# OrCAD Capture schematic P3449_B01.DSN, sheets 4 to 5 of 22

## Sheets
4 0018_CAM Connector: size Custom
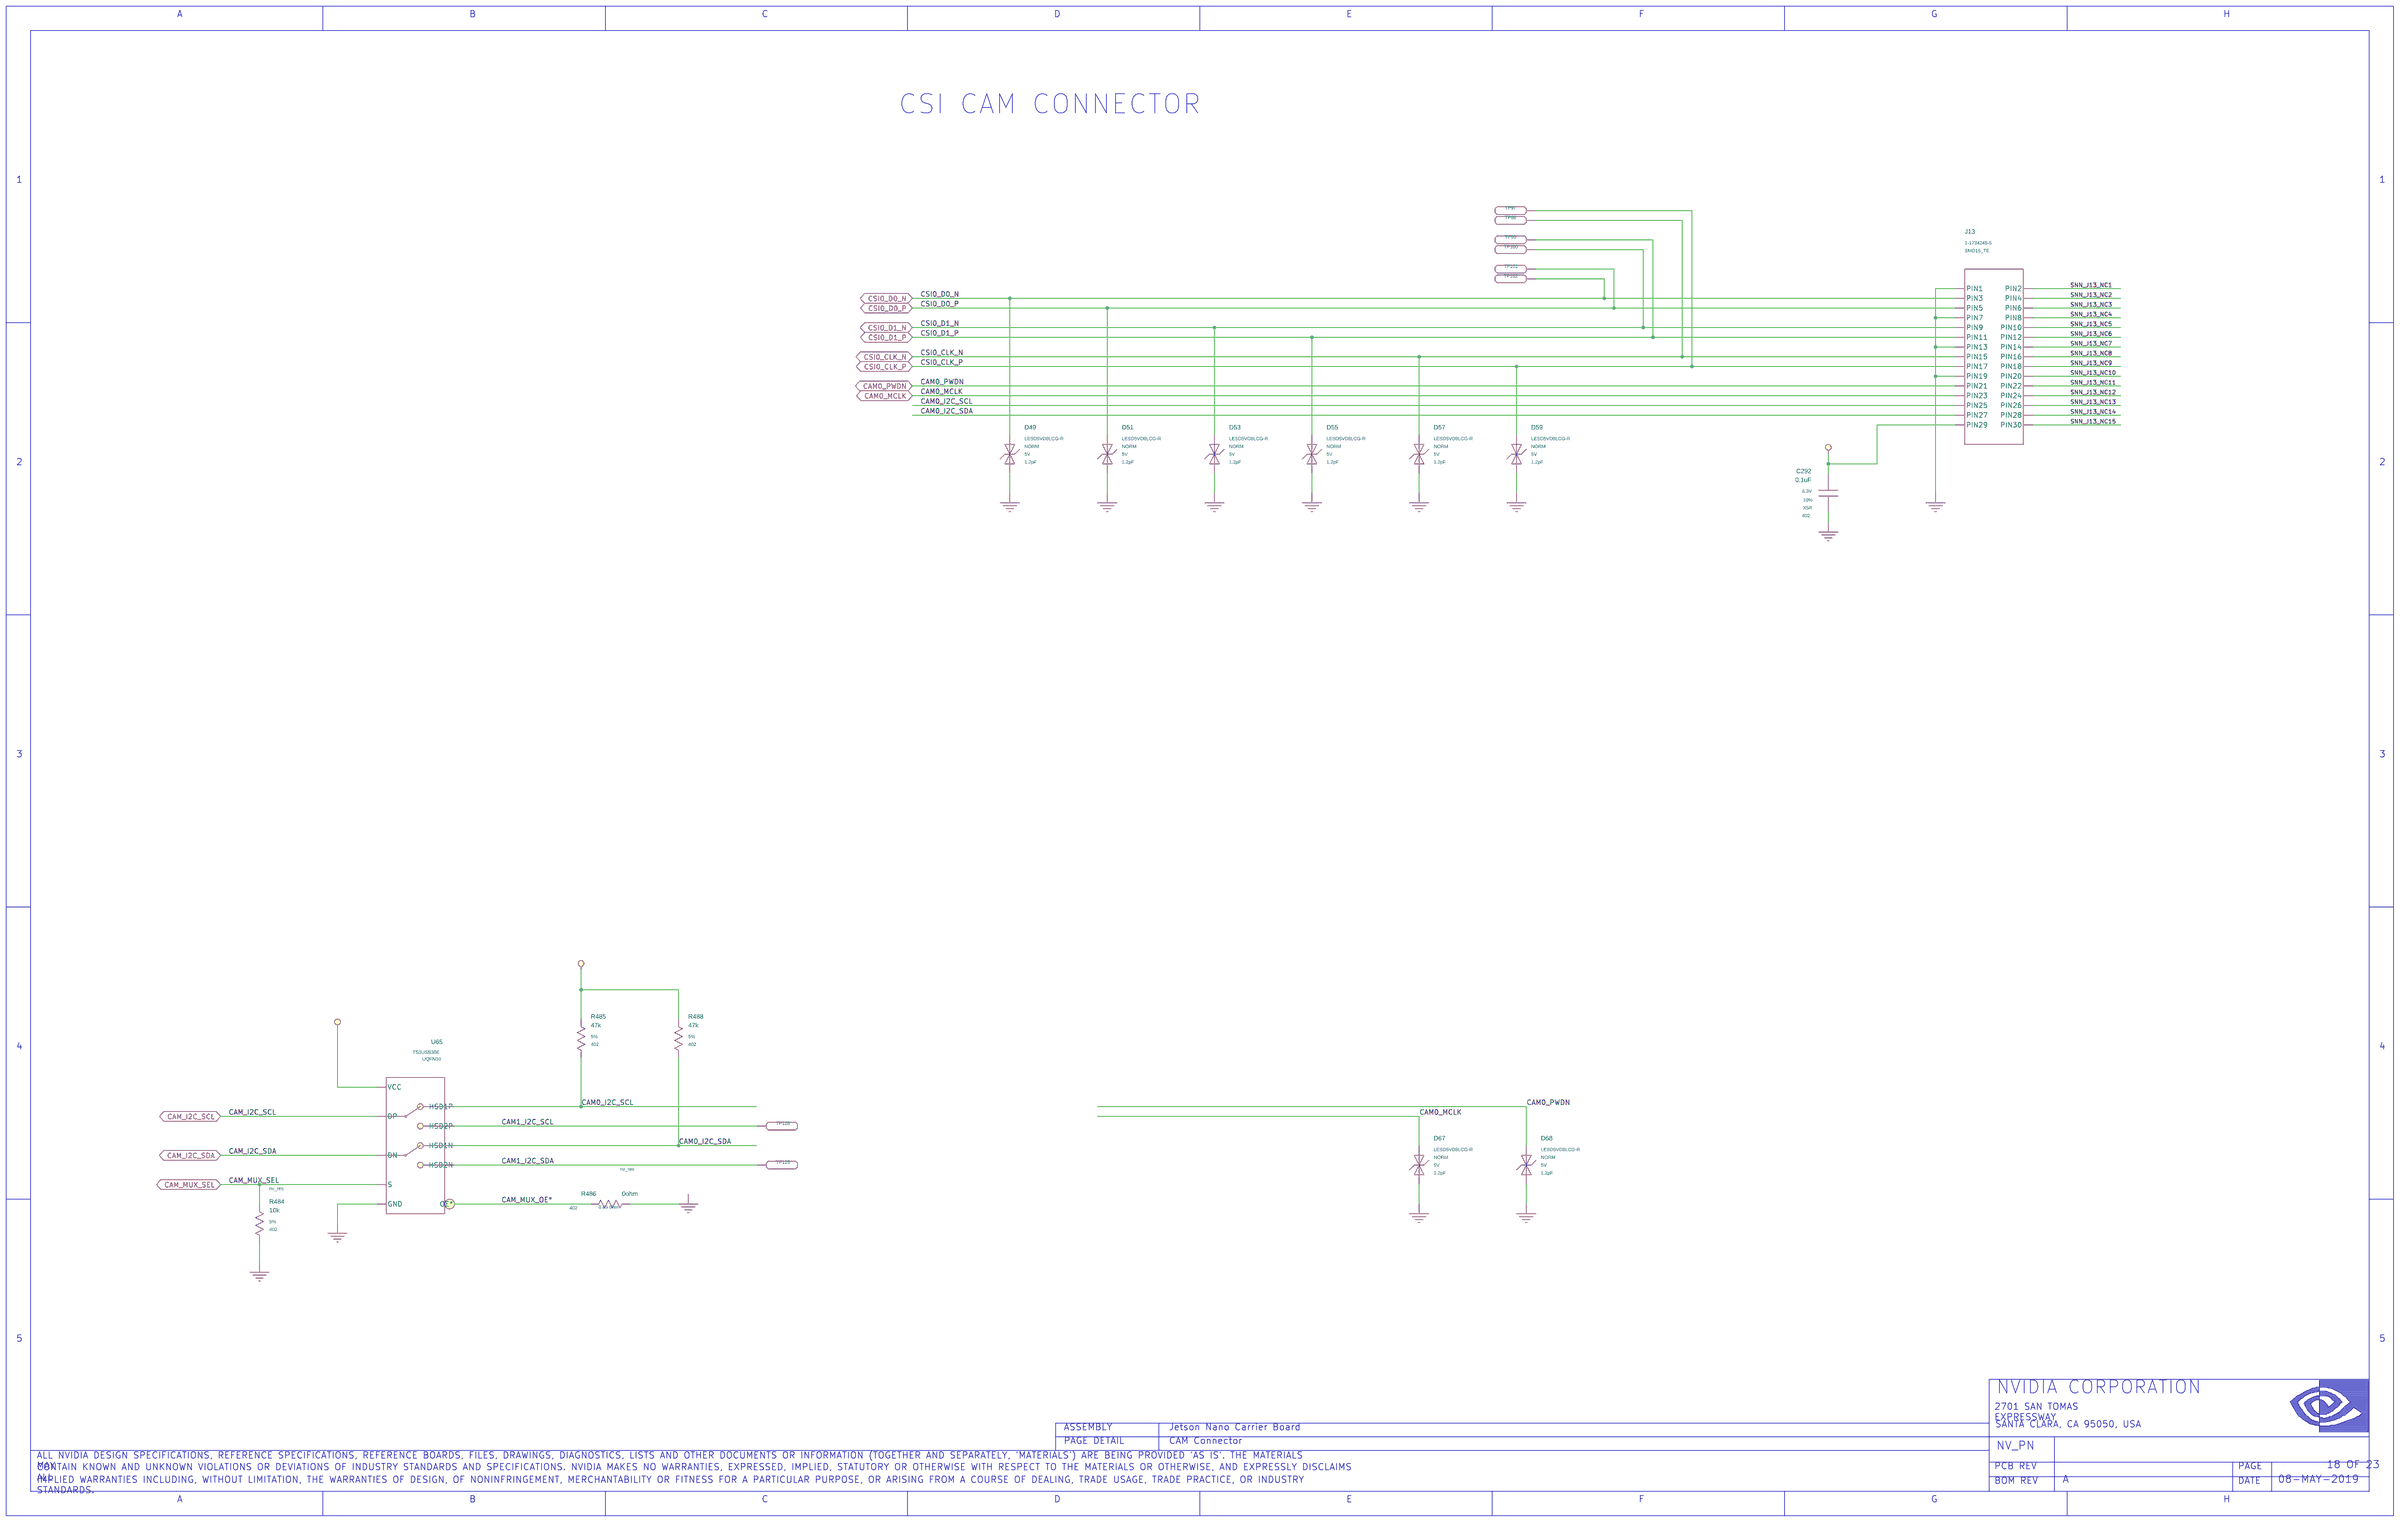
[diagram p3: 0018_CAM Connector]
5 0017_DisplayPort: size Custom
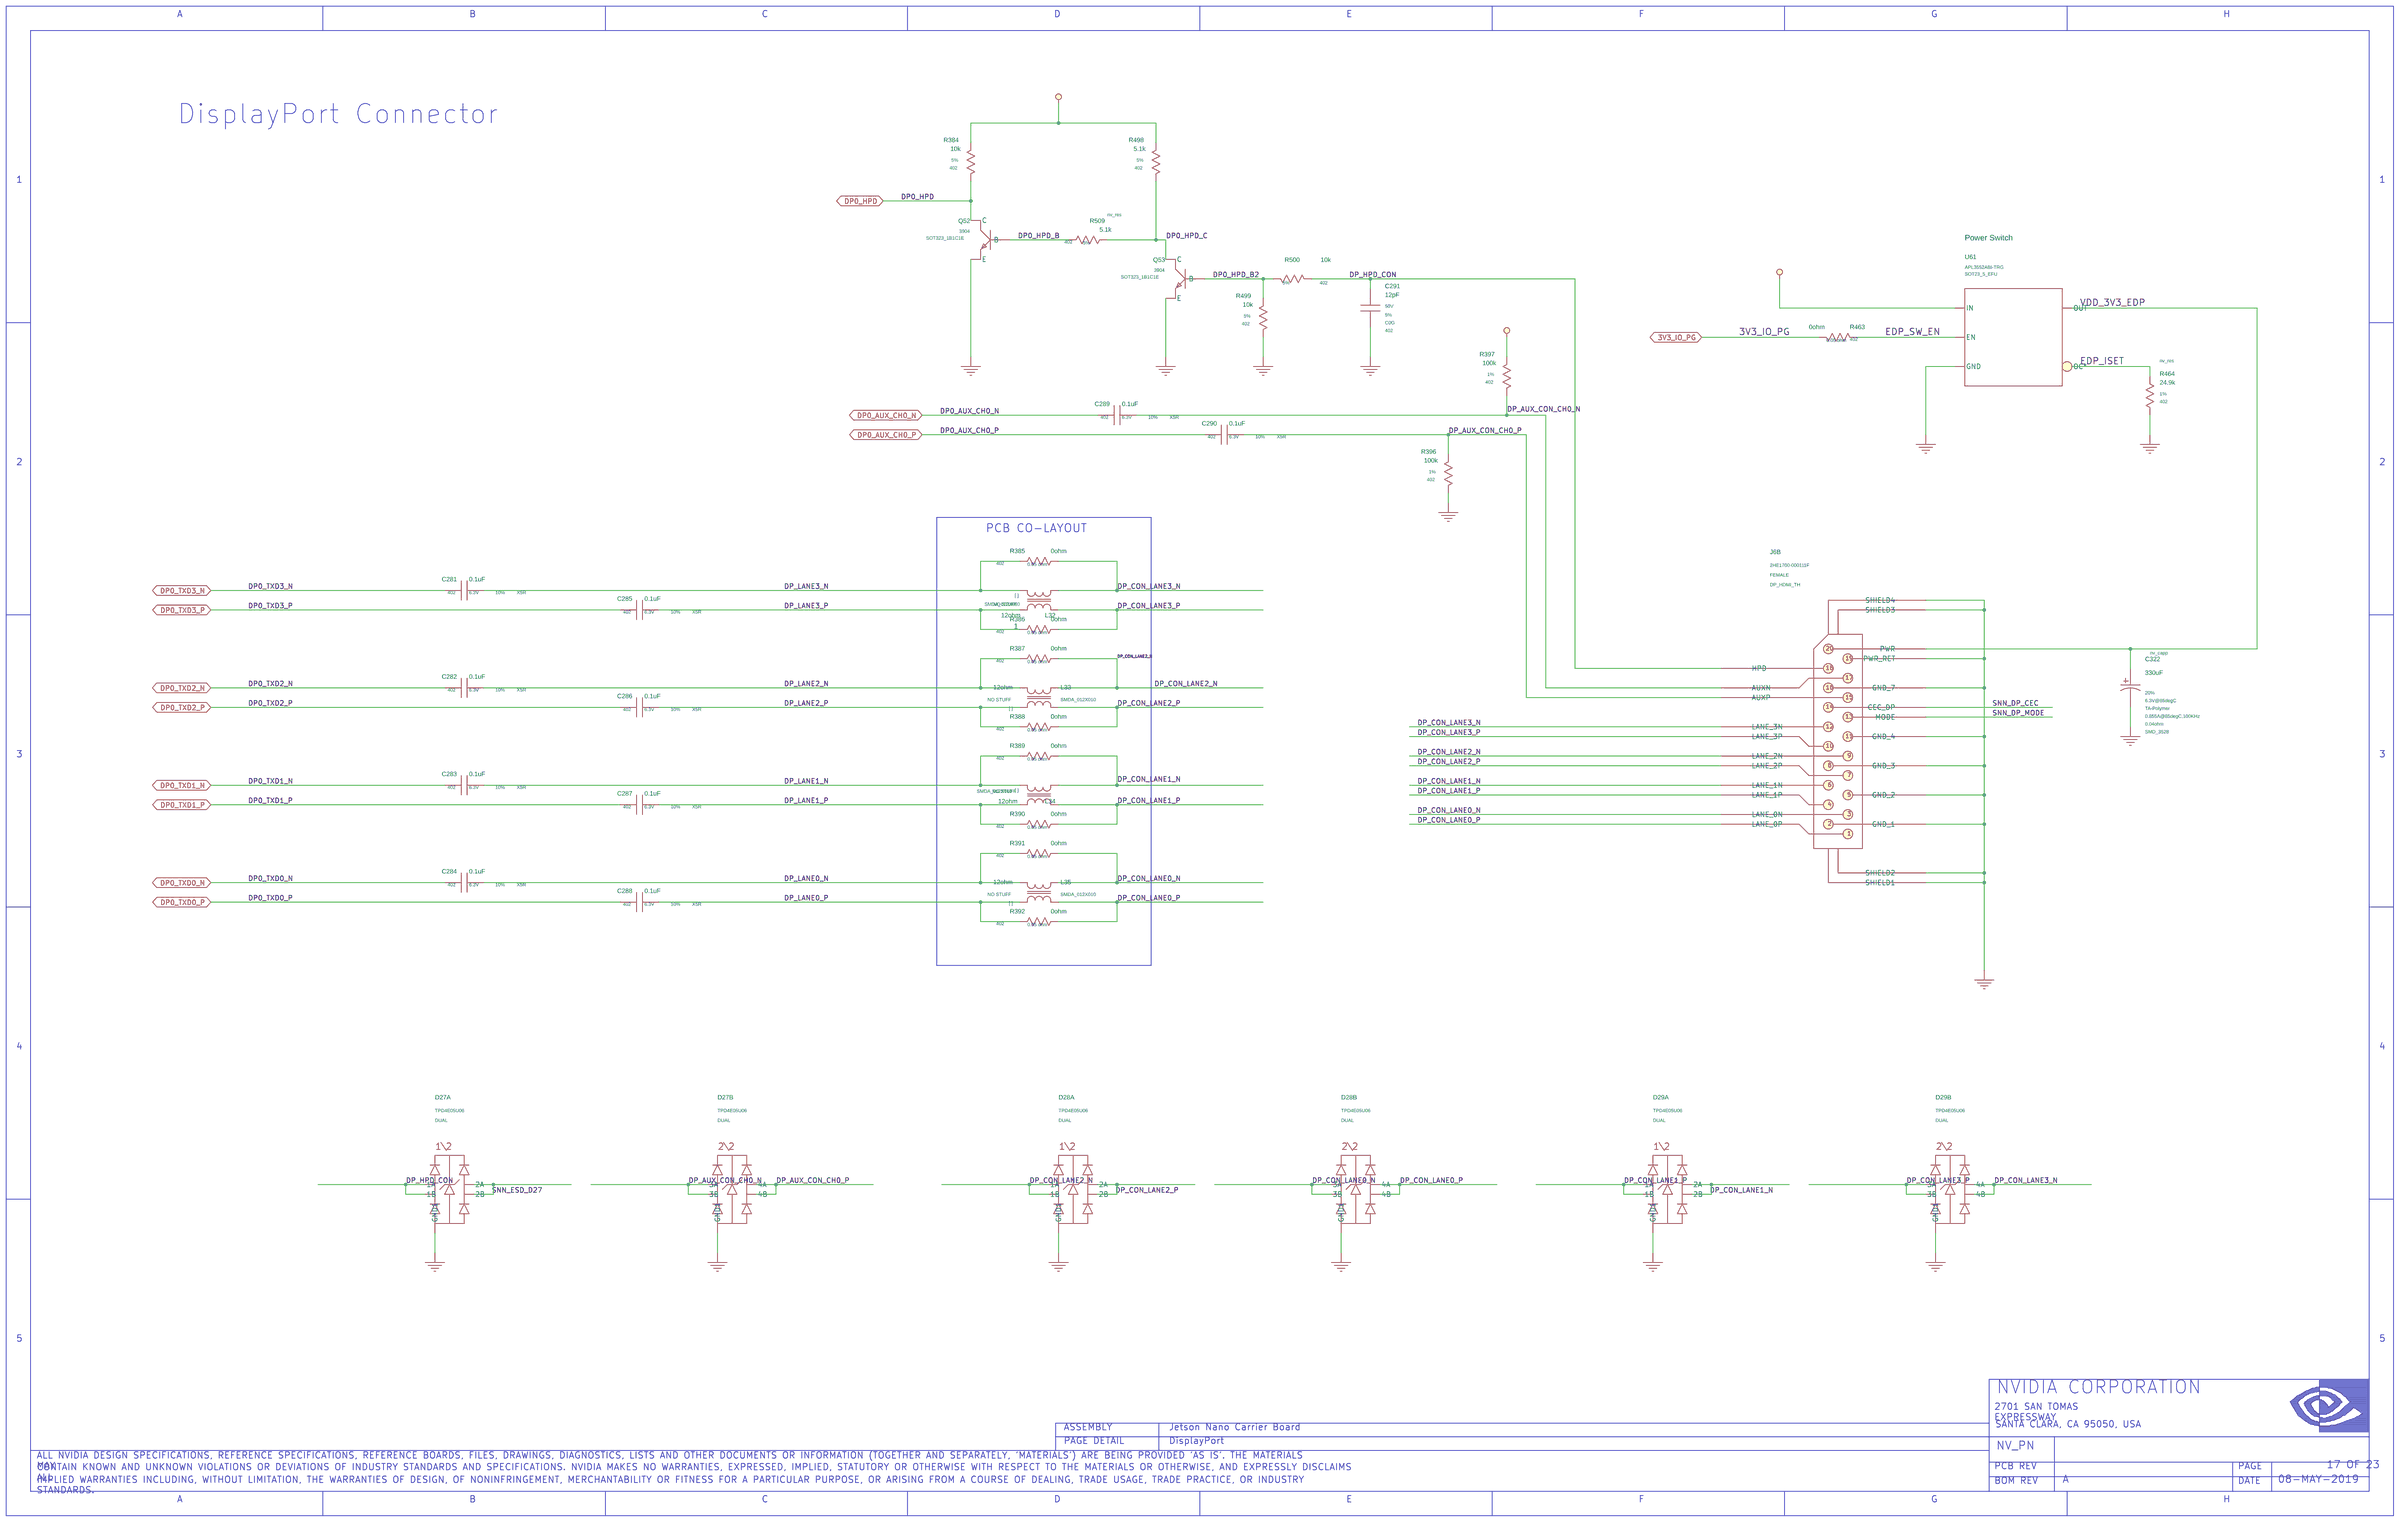
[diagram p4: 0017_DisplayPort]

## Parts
sheet 0017_DisplayPort
C281  0.1uF  [402]
C282  0.1uF  [402]
C283  0.1uF  [402]
C284  0.1uF  [402]
C285  0.1uF  [402]
C286  0.1uF  [402]
C287  0.1uF  [402]
C288  0.1uF  [402]
C289  0.1uF  [402]
C290  0.1uF  [402]
C291  12pF  [402]
C322  330uF  [CAP_SMD_3528]
D27  D_ESD_DIFFPAIR  [TSLP10_P050_025X010]  (sections A,B)
D28  D_ESD_DIFFPAIR  [TSLP10_P050_025X010]  (sections A,B)
D29  D_ESD_DIFFPAIR  [TSLP10_P050_025X010]  (sections A,B)
J6  CON_HDMI_DISPLAYPORT  [CON_HDMI_019_DP_020_TH_RA_F_181X180_B]  (sections A,B)
L32  12ohm  [IND_NONRKO_SMD_012X010]
L33  12ohm  [IND_NONRKO_SMD_012X010]
L34  12ohm  [IND_NONRKO_SMD_012X010]
L35  12ohm  [IND_NONRKO_SMD_012X010]
Q52  Q_NPN  [SOT323_D]
Q53  Q_NPN  [SOT323_D]
R384  10k  [402]
R385  0ohm  [402]
R386  0ohm  [402]
R387  0ohm  [402]
R388  0ohm  [402]
R389  0ohm  [402]
R390  0ohm  [402]
R391  0ohm  [402]
R392  0ohm  [402]
R396  100k  [402]
R397  100k  [402]
R463  0ohm  [402]
R464  24.9k  [402]
R498  5.1k  [402]
R499  10k  [402]
R500  10k  [402]
R509  5.1k  [402]
U61  U_PWR_SW_UL  [SOT23_5]
sheet 0018_CAM Connector
C292  0.1uF  [402]
D49  D_ESD  [DIODE_SMD_010X060]
D51  D_ESD  [DIODE_SMD_010X060]
D53  D_ESD  [DIODE_SMD_010X060]
D55  D_ESD  [DIODE_SMD_010X060]
D57  D_ESD  [DIODE_SMD_010X060]
D59  D_ESD  [DIODE_SMD_010X060]
D67  D_ESD  [DIODE_SMD_010X060]
D68  D_ESD  [DIODE_SMD_010X060]
J13  CON_FPC_15  [CON_FFC_030_SMD_ST_F_P010_ZIF]
R484  10k  [402]
R485  47k  [402]
R486  0ohm  [402]
R488  47k  [402]
TP97  LABTESTPOINT  [LTPB071C125D045C025P]
TP98  LABTESTPOINT  [LTPB071C125D045C025P]
TP99  LABTESTPOINT  [LTPB071C125D045C025P]
TP100  LABTESTPOINT  [LTPB071C125D045C025P]
TP101  LABTESTPOINT  [LTPB071C125D045C025P]
TP102  LABTESTPOINT  [LTPB071C125D045C025P]
TP128  LABTESTPOINT  [LTPB071C125D045C025P]
TP129  LABTESTPOINT  [LTPB071C125D045C025P]
U65  U_SW_ANA_USB  [QFN010R_P040_0018X0014]

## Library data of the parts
C281 = C: ASSEMBLY: EDP; CDS_LIB: discrete; CDS_PART_NAME: C_0402-0.1UF,X5R,10%,6.3V,039-0007-000; CDS_PHYS_PART_NAME: C_0402-0.1UF,X5R,10%,6.3V,039-0007-000-0.1UF,039-0007-000; CDS_SEC: 1; DEVICE_TYPENAME: C_0402-01UFX5R1063V039-0007-000-01UF039-0007-000; DRAWING: @P3449_B01_LIB.P3449_B01(SCH_1):PAGE17; MAT: X5R; MAX_VOLTAGE: 6.3V; NO_XNET: 1; NV_PN: 039-0007-000; PATH: I22; PHYS_PAGE: 17; ROT: 0; SEC: 1; SIGNAL_MODEL: nv_cap; TOL: 10%; VER: 2; XY: (-9800,4600)
C282 = C: ASSEMBLY: EDP; CDS_LIB: discrete; CDS_PART_NAME: C_0402-0.1UF,X5R,10%,6.3V,039-0007-000; CDS_PHYS_PART_NAME: C_0402-0.1UF,X5R,10%,6.3V,039-0007-000-0.1UF,039-0007-000; CDS_SEC: 1; DEVICE_TYPENAME: C_0402-01UFX5R1063V039-0007-000-01UF039-0007-000; DRAWING: @P3449_B01_LIB.P3449_B01(SCH_1):PAGE17; MAT: X5R; MAX_VOLTAGE: 6.3V; NO_XNET: 1; NV_PN: 039-0007-000; PATH: I28; PHYS_PAGE: 17; ROT: 0; SEC: 1; SIGNAL_MODEL: nv_cap; TOL: 10%; VER: 2; XY: (-9800,4100)
C283 = C: ASSEMBLY: EDP; CDS_LIB: discrete; CDS_PART_NAME: C_0402-0.1UF,X5R,10%,6.3V,039-0007-000; CDS_PHYS_PART_NAME: C_0402-0.1UF,X5R,10%,6.3V,039-0007-000-0.1UF,039-0007-000; CDS_SEC: 1; DEVICE_TYPENAME: C_0402-01UFX5R1063V039-0007-000-01UF039-0007-000; DRAWING: @P3449_B01_LIB.P3449_B01(SCH_1):PAGE17; MAT: X5R; MAX_VOLTAGE: 6.3V; NO_XNET: 1; NV_PN: 039-0007-000; PATH: I29; PHYS_PAGE: 17; ROT: 0; SEC: 1; SIGNAL_MODEL: nv_cap; TOL: 10%; VER: 2; XY: (-9800,3600)
C284 = C: ASSEMBLY: EDP; CDS_LIB: discrete; CDS_PART_NAME: C_0402-0.1UF,X5R,10%,6.3V,039-0007-000; CDS_PHYS_PART_NAME: C_0402-0.1UF,X5R,10%,6.3V,039-0007-000-0.1UF,039-0007-000; CDS_SEC: 1; DEVICE_TYPENAME: C_0402-01UFX5R1063V039-0007-000-01UF039-0007-000; DRAWING: @P3449_B01_LIB.P3449_B01(SCH_1):PAGE17; MAT: X5R; MAX_VOLTAGE: 6.3V; NO_XNET: 1; NV_PN: 039-0007-000; PATH: I27; PHYS_PAGE: 17; ROT: 0; SEC: 1; SIGNAL_MODEL: nv_cap; TOL: 10%; VER: 2; XY: (-9800,3100)
C285 = C: ASSEMBLY: EDP; CDS_LIB: discrete; CDS_PART_NAME: C_0402-0.1UF,X5R,10%,6.3V,039-0007-000; CDS_PHYS_PART_NAME: C_0402-0.1UF,X5R,10%,6.3V,039-0007-000-0.1UF,039-0007-000; CDS_SEC: 1; DEVICE_TYPENAME: C_0402-01UFX5R1063V039-0007-000-01UF039-0007-000; DRAWING: @P3449_B01_LIB.P3449_B01(SCH_1):PAGE17; MAT: X5R; MAX_VOLTAGE: 6.3V; NO_XNET: 1; NV_PN: 039-0007-000; PATH: I23; PHYS_PAGE: 17; ROT: 0; SEC: 1; SIGNAL_MODEL: nv_cap; TOL: 10%; VER: 2; XY: (-8900,4500)
C286 = C: ASSEMBLY: EDP; CDS_LIB: discrete; CDS_PART_NAME: C_0402-0.1UF,X5R,10%,6.3V,039-0007-000; CDS_PHYS_PART_NAME: C_0402-0.1UF,X5R,10%,6.3V,039-0007-000-0.1UF,039-0007-000; CDS_SEC: 1; DEVICE_TYPENAME: C_0402-01UFX5R1063V039-0007-000-01UF039-0007-000; DRAWING: @P3449_B01_LIB.P3449_B01(SCH_1):PAGE17; MAT: X5R; MAX_VOLTAGE: 6.3V; NO_XNET: 1; NV_PN: 039-0007-000; PATH: I24; PHYS_PAGE: 17; ROT: 0; SEC: 1; SIGNAL_MODEL: nv_cap; TOL: 10%; VER: 2; XY: (-8900,4000)
C287 = C: ASSEMBLY: EDP; CDS_LIB: discrete; CDS_PART_NAME: C_0402-0.1UF,X5R,10%,6.3V,039-0007-000; CDS_PHYS_PART_NAME: C_0402-0.1UF,X5R,10%,6.3V,039-0007-000-0.1UF,039-0007-000; CDS_SEC: 1; DEVICE_TYPENAME: C_0402-01UFX5R1063V039-0007-000-01UF039-0007-000; DRAWING: @P3449_B01_LIB.P3449_B01(SCH_1):PAGE17; MAT: X5R; MAX_VOLTAGE: 6.3V; NO_XNET: 1; NV_PN: 039-0007-000; PATH: I25; PHYS_PAGE: 17; ROT: 0; SEC: 1; SIGNAL_MODEL: nv_cap; TOL: 10%; VER: 2; XY: (-8900,3500)
C288 = C: ASSEMBLY: EDP; CDS_LIB: discrete; CDS_PART_NAME: C_0402-0.1UF,X5R,10%,6.3V,039-0007-000; CDS_PHYS_PART_NAME: C_0402-0.1UF,X5R,10%,6.3V,039-0007-000-0.1UF,039-0007-000; CDS_SEC: 1; DEVICE_TYPENAME: C_0402-01UFX5R1063V039-0007-000-01UF039-0007-000; DRAWING: @P3449_B01_LIB.P3449_B01(SCH_1):PAGE17; MAT: X5R; MAX_VOLTAGE: 6.3V; NO_XNET: 1; NV_PN: 039-0007-000; PATH: I26; PHYS_PAGE: 17; ROT: 0; SEC: 1; SIGNAL_MODEL: nv_cap; TOL: 10%; VER: 2; XY: (-8900,3000)
C289 = C: ASSEMBLY: EDP; CDS_LIB: discrete; CDS_PART_NAME: C_0402-0.1UF,X5R,10%,6.3V,039-0007-000; CDS_PHYS_PART_NAME: C_0402-0.1UF,X5R,10%,6.3V,039-0007-000-0.1UF,039-0007-000; CDS_SEC: 1; DEVICE_TYPENAME: C_0402-01UFX5R1063V039-0007-000-01UF039-0007-000; DRAWING: @P3449_B01_LIB.P3449_B01(SCH_1):PAGE17; MAT: X5R; MAX_VOLTAGE: 6.3V; NV_PN: 039-0007-000; PATH: I38; PHYS_PAGE: 17; ROT: 0; SEC: 1; SIGNAL_MODEL: nv_cap; TOL: 10%; VER: 2; XY: (-6450,5500)
C290 = C: ASSEMBLY: EDP; CDS_LIB: discrete; CDS_PART_NAME: C_0402-0.1UF,X5R,10%,6.3V,039-0007-000; CDS_PHYS_PART_NAME: C_0402-0.1UF,X5R,10%,6.3V,039-0007-000-0.1UF,039-0007-000; CDS_SEC: 1; DEVICE_TYPENAME: C_0402-01UFX5R1063V039-0007-000-01UF039-0007-000; DRAWING: @P3449_B01_LIB.P3449_B01(SCH_1):PAGE17; MAT: X5R; MAX_VOLTAGE: 6.3V; NV_PN: 039-0007-000; PATH: I39; PHYS_PAGE: 17; ROT: 0; SEC: 1; SIGNAL_MODEL: nv_cap; TOL: 10%; VER: 2; XY: (-5900,5400)
C291 = C#1: ASSEMBLY: EDP; CDS_LIB: discrete; CDS_PART_NAME: C_0402-12PF,C0G,5%,50V,035-0014-000; CDS_PHYS_PART_NAME: C_0402-12PF,C0G,5%,50V,035-0014-000-035-0014-000,12PF; CDS_SEC: 1; CHIPS_PART_NAME: C; DEVICE_TYPENAME: C_0402-12PFC0G550V035-0014-000-035-0014-00012PF; DRAWING: @P3449_B01_LIB.P3449_B01(SCH_1):PAGE17; ESL: N/A; ESR: N/A; MAT: C0G; MAX_VOLTAGE: 50V; NV_PN: 035-0014-000; PATH: I45; PHYS_PAGE: 17; ROT: 0; SEC: 1; SIGNAL_MODEL: nv_cap; TOL: 5%; VER: 1; XY: (-5150,6050)
C322 = C_POL: ASSEMBLY: EDP; CDS_LIB: discrete; CDS_PART_NAME: C_POL_SMD_3528-330UF,TA-POLYMER,20%,6.3V@85DEGC,0.04OHM,9.999UH,0.855A@85DEGC,100KHZ,032-0696-000; CDS_PHYS_PART_NAME: C_POL_SMD_3528-330UF,TA-POLYMER,20%,6.3V@85DEGC,0.04OHM,9.999UH,0.855A@85DEGC,100KHZ,032-0696-000-032-0696-000,330UF; CDS_SEC: 1; DEVICE_TYPENAME: C_POL_SMD_3528-330UFTA-POLYMER2063V85DEGC004OHM9999UH0855A85DEGC100KHZ032-0696-000-032-0696-000330UF; DRAWING: @P3449_B01_LIB.P3449_B01(SCH_1):PAGE17; ESL: 9.999uH; ESR: 0.04ohm; MAT: TA-Polymer; MAX_VOLTAGE: 6.3V@85degC; NV_PN: 032-0696-000; PACK_TYPE: SMD_3528; PATH: I89; PHYS_PAGE: 17; RIPPLE_CURRENT: 0.855A@85degC,100KHz; ROT: 0; SEC: 1; SIGNAL_MODEL: nv_capp; TOL: 20%; VER: 1; XY: (-1250,4100)
D27 = D_ESD_DIFFPAIR: ASSEMBLY: EDP; BREAKDOWN_VOLTAGE_MIN_TYP: 6V; CAPACITANCE_MAX_TYP: 0.5pF; CDS_LIB: discrete; CDS_PART_NAME: D_ESD_DIFFPAIR_DUAL-TPD4E05U06,2 DIFFPAIR,UNI-DIRECTIONAL,5.5V,10UA,6V,10V@1A,0.5PF,090-0231-000; CDS_PHYS_PART_NAME: D_ESD_DIFFPAIR_DUAL-TPD4E05U06,2 DIFFPAIR,UNI-DIRECTIONAL,5.5V,10UA,6V,10V@1A,0.5PF,090-0231-000-090-0231-000; CDS_SEC: 1; CLAMPING_VOLTAGE: 10V@1A; CONFIGURATION: 2 Diffpair; CaptureCellPackProp: D_ESD_DIFFPAIRA; DEVICE_TYPENAME: D_ESD_DIFFPAIR_DUAL-TPD4E05U062DIFFPAIRUNI-DIRECTIONAL55V10UA6V10V1A05PF090-0231-000-090-0231-000; DRAWING: @P3449_B01_LIB.P3449_B01(SCH_1):PAGE17; MAX_REVERSE_LEAKAGE_CURRENT: 10uA; MAX_REVERSE_VOLTAGE: 5.5V; NV_NAME: TPD4E05U06; NV_PN: 090-0231-000; PACK_TYPE: DUAL; PATH: I64; PHYS_PAGE: 17; POLARITY: Uni-Directional; ROT: 0; SEC: 1; VER: 1; XY: (-9900,1550)
D28 = D_ESD_DIFFPAIR: ASSEMBLY: EDP; BREAKDOWN_VOLTAGE_MIN_TYP: 6V; CAPACITANCE_MAX_TYP: 0.5pF; CDS_LIB: discrete; CDS_PART_NAME: D_ESD_DIFFPAIR_DUAL-TPD4E05U06,2 DIFFPAIR,UNI-DIRECTIONAL,5.5V,10UA,6V,10V@1A,0.5PF,090-0231-000; CDS_PHYS_PART_NAME: D_ESD_DIFFPAIR_DUAL-TPD4E05U06,2 DIFFPAIR,UNI-DIRECTIONAL,5.5V,10UA,6V,10V@1A,0.5PF,090-0231-000-090-0231-000; CDS_SEC: 2; CLAMPING_VOLTAGE: 10V@1A; CONFIGURATION: 2 Diffpair; CaptureCellPackProp: D_ESD_DIFFPAIRB; DEVICE_TYPENAME: D_ESD_DIFFPAIR_DUAL-TPD4E05U062DIFFPAIRUNI-DIRECTIONAL55V10UA6V10V1A05PF090-0231-000-090-0231-000; DRAWING: @P3449_B01_LIB.P3449_B01(SCH_1):PAGE17; MAX_REVERSE_LEAKAGE_CURRENT: 10uA; MAX_REVERSE_VOLTAGE: 5.5V; NV_NAME: TPD4E05U06; NV_PN: 090-0231-000; PACK_TYPE: DUAL; PATH: I69; PHYS_PAGE: 17; POLARITY: Uni-Directional; ROT: 0; SEC: 2; VER: 2; XY: (-5250,1550)
D29 = D_ESD_DIFFPAIR: ASSEMBLY: EDP; BREAKDOWN_VOLTAGE_MIN_TYP: 6V; CAPACITANCE_MAX_TYP: 0.5pF; CDS_LIB: discrete; CDS_PART_NAME: D_ESD_DIFFPAIR_DUAL-TPD4E05U06,2 DIFFPAIR,UNI-DIRECTIONAL,5.5V,10UA,6V,10V@1A,0.5PF,090-0231-000; CDS_PHYS_PART_NAME: D_ESD_DIFFPAIR_DUAL-TPD4E05U06,2 DIFFPAIR,UNI-DIRECTIONAL,5.5V,10UA,6V,10V@1A,0.5PF,090-0231-000-090-0231-000; CDS_SEC: 1; CLAMPING_VOLTAGE: 10V@1A; CONFIGURATION: 2 Diffpair; CaptureCellPackProp: D_ESD_DIFFPAIRA; DEVICE_TYPENAME: D_ESD_DIFFPAIR_DUAL-TPD4E05U062DIFFPAIRUNI-DIRECTIONAL55V10UA6V10V1A05PF090-0231-000-090-0231-000; DRAWING: @P3449_B01_LIB.P3449_B01(SCH_1):PAGE17; MAX_REVERSE_LEAKAGE_CURRENT: 10uA; MAX_REVERSE_VOLTAGE: 5.5V; NV_NAME: TPD4E05U06; NV_PN: 090-0231-000; PACK_TYPE: DUAL; PATH: I75; PHYS_PAGE: 17; POLARITY: Uni-Directional; ROT: 0; SEC: 1; VER: 1; XY: (-3650,1550)
J6 = CON_HDMI_DISPLAYPORT: ANGLE: 90; ASSEMBLY: HDMI; CDS_LIB: electro_mechanic; CDS_PART_NAME: CON_HDMI_DISPLAYPORT_DP_HDMI_TH-2HE1700-000111F,FEMALE,1.4MM,90,YES,YES,YES,YES,YES,40 MV,500 MA,064-0374-000; CDS_PHYS_PART_NAME: CON_HDMI_DISPLAYPORT_DP_HDMI_TH-2HE1700-000111F,FEMALE,1.4MM,90,YES,YES,YES,YES,YES,40 MV,500 MA,064-0374-000-064-0374-000; CDS_SEC: 1; CaptureCellPackProp: CON_HDMI_DISPLAYPORTA; DEVICE_TYPENAME: CON_HDMI_DISPLAYPORT_DP_HDMI_TH-2HE1700-000111FFEMALE14MM90YESYESYESYESYES40MV500MA064-0374-000-064-0374-000; DRAWING: @P3449_B01_LIB.P3449_B01(SCH_1):PAGE16; EMI_GROUND_TAB: YES; GENDER: FEMALE; LATCHING: YES; MAX_CURRENT: 500 mA; MAX_VOLTAGE: 40 mV; NV_NAME: 2HE1700-000111F; NV_PN: 064-0374-000; PACK_TYPE: DP_HDMI_TH; PATH: I389; PHYS_PAGE: 16; PITCH: 1.4mm; REFLOW: YES; ROT: 0; SEC: 1; SHIELDED: YES; SHROUDED: YES; VER: 1; XY: (-600,2950)
L32 = L_CMF_4P#1: ASSEMBLY: EDP; CDS_LIB: discrete; CDS_PART_NAME: L_CMF_4P_SMDA_012X010-12OHM,[ ],25%,0.1A,1.5OHM,MCZ1210DH120L2TA0G,102-0066-000; CDS_PHYS_PART_NAME: L_CMF_4P_SMDA_012X010-12OHM,[ ],25%,0.1A,1.5OHM,MCZ1210DH120L2TA0G,102-0066-000-102-0066-000,12OHM; CDS_SEC: 1; CHIPS_PART_NAME: L_CMF_4P; DC_RESISTANCE: 1.5ohm; DEVICE_TYPENAME: L_CMF_4P_SMDA_012X010-12OHM2501A15OHMMCZ1210DH120L2TA0G102-0066-000-102-0066-00012OHM; DRAWING: @P3449_B01_LIB.P3449_B01(SCH_1):PAGE17; MAT: [ ]; MAX_CURRENT: 0.1A; NO_XNET_CONNECTION: 1; NV_NAME: MCZ1210DH120L2TA0G; NV_PN: 102-0066-000; PACK_TYPE: SMDA_012X010; PATH: I11; PHYS_PAGE: 17; PLACEMENT_NOTE: CoLayout with R563, R565; ROT: 4; SEC: 1; SEC_TYPE: SMDA_012X010; SIGNAL_MODEL: nv_ind_cmf_4p; SKU: NO STUFF; TOL: 25%; VER: 1; XY: (-6850,4550)
L33 = L_CMF_4P#1: ASSEMBLY: EDP; CDS_LIB: discrete; CDS_PART_NAME: L_CMF_4P_SMDA_012X010-12OHM,[ ],25%,0.1A,1.5OHM,MCZ1210DH120L2TA0G,102-0066-000; CDS_PHYS_PART_NAME: L_CMF_4P_SMDA_012X010-12OHM,[ ],25%,0.1A,1.5OHM,MCZ1210DH120L2TA0G,102-0066-000-102-0066-000,12OHM; CDS_SEC: 1; CHIPS_PART_NAME: L_CMF_4P; DC_RESISTANCE: 1.5ohm; DEVICE_TYPENAME: L_CMF_4P_SMDA_012X010-12OHM2501A15OHMMCZ1210DH120L2TA0G102-0066-000-102-0066-00012OHM; DRAWING: @P3449_B01_LIB.P3449_B01(SCH_1):PAGE17; MAT: [ ]; MAX_CURRENT: 0.1A; NV_NAME: MCZ1210DH120L2TA0G; NV_PN: 102-0066-000; PACK_TYPE: SMDA_012X010; PATH: I14; PHYS_PAGE: 17; PLACEMENT_NOTE: CoLayout with R568, R571; ROT: 2; SEC: 1; SEC_TYPE: SMDA_012X010; SIGNAL_MODEL: nv_ind_cmf_4p; SKU: NO STUFF; TOL: 25%; VER: 1; XY: (-6850,4050)
L34 = L_CMF_4P#1: ASSEMBLY: EDP; CDS_LIB: discrete; CDS_PART_NAME: L_CMF_4P_SMDA_012X010-12OHM,[ ],25%,0.1A,1.5OHM,MCZ1210DH120L2TA0G,102-0066-000; CDS_PHYS_PART_NAME: L_CMF_4P_SMDA_012X010-12OHM,[ ],25%,0.1A,1.5OHM,MCZ1210DH120L2TA0G,102-0066-000-102-0066-000,12OHM; CDS_SEC: 1; CHIPS_PART_NAME: L_CMF_4P; DC_RESISTANCE: 1.5ohm; DEVICE_TYPENAME: L_CMF_4P_SMDA_012X010-12OHM2501A15OHMMCZ1210DH120L2TA0G102-0066-000-102-0066-00012OHM; DRAWING: @P3449_B01_LIB.P3449_B01(SCH_1):PAGE17; MAT: [ ]; MAX_CURRENT: 0.1A; NV_NAME: MCZ1210DH120L2TA0G; NV_PN: 102-0066-000; PACK_TYPE: SMDA_012X010; PATH: I17; PHYS_PAGE: 17; PLACEMENT_NOTE: CoLayout with R577, R579; ROT: 4; SEC: 1; SEC_TYPE: SMDA_012X010; SIGNAL_MODEL: nv_ind_cmf_4p; SKU: NO STUFF; TOL: 25%; VER: 1; XY: (-6850,3550)
L35 = L_CMF_4P#1: ASSEMBLY: EDP; CDS_LIB: discrete; CDS_PART_NAME: L_CMF_4P_SMDA_012X010-12OHM,[ ],25%,0.1A,1.5OHM,MCZ1210DH120L2TA0G,102-0066-000; CDS_PHYS_PART_NAME: L_CMF_4P_SMDA_012X010-12OHM,[ ],25%,0.1A,1.5OHM,MCZ1210DH120L2TA0G,102-0066-000-102-0066-000,12OHM; CDS_SEC: 1; CHIPS_PART_NAME: L_CMF_4P; DC_RESISTANCE: 1.5ohm; DEVICE_TYPENAME: L_CMF_4P_SMDA_012X010-12OHM2501A15OHMMCZ1210DH120L2TA0G102-0066-000-102-0066-00012OHM; DRAWING: @P3449_B01_LIB.P3449_B01(SCH_1):PAGE17; MAT: [ ]; MAX_CURRENT: 0.1A; NV_NAME: MCZ1210DH120L2TA0G; NV_PN: 102-0066-000; PACK_TYPE: SMDA_012X010; PATH: I20; PHYS_PAGE: 17; PLACEMENT_NOTE: CoLayout with R583, R584; ROT: 2; SEC: 1; SEC_TYPE: SMDA_012X010; SIGNAL_MODEL: nv_ind_cmf_4p; SKU: NO STUFF; TOL: 25%; VER: 1; XY: (-6850,3050)
Q52 = Q_NPN: ASSEMBLY: SHUTDOWN; CDS_LIB: discrete; CDS_PART_NAME: Q_NPN_SOT323_1B1C1E-3904,40V,0.3V,0.2A,0.2A,6V,0.15W,300-1128-000; CDS_PHYS_PART_NAME: Q_NPN_SOT323_1B1C1E-3904,40V,0.3V,0.2A,0.2A,6V,0.15W,300-1128-000-300-1128-000; CDS_SEC: 1; CONTINUOUS_CURRENT: 0.2A; DEVICE_TYPENAME: Q_NPN_SOT323_1B1C1E-390440V03V02A02A6V015W300-1128-000-300-1128-000; DRAWING: @P3449_B01_LIB.P3449_B01(SCH_1):PAGE17; MAX_CURRENT: 0.2A; MAX_VOLTAGE: 40V; MAX_WATTAGE: 0.15W; NV_NAME: 3904; NV_PN: 300-1128-000; PACK_TYPE: SOT323_1B1C1E; PATH: I90; PHYS_PAGE: 17; ROT: 2; SEC: 1; VER: 1; V_BE_GS: 6V; V_CE_SAT: 0.3V; XY: (-7100,6400)
Q53 = Q_NPN: ASSEMBLY: SHUTDOWN; CDS_LIB: discrete; CDS_PART_NAME: Q_NPN_SOT323_1B1C1E-3904,40V,0.3V,0.2A,0.2A,6V,0.15W,300-1128-000; CDS_PHYS_PART_NAME: Q_NPN_SOT323_1B1C1E-3904,40V,0.3V,0.2A,0.2A,6V,0.15W,300-1128-000-300-1128-000; CDS_SEC: 1; CONTINUOUS_CURRENT: 0.2A; DEVICE_TYPENAME: Q_NPN_SOT323_1B1C1E-390440V03V02A02A6V015W300-1128-000-300-1128-000; DRAWING: @P3449_B01_LIB.P3449_B01(SCH_1):PAGE17; MAX_CURRENT: 0.2A; MAX_VOLTAGE: 40V; MAX_WATTAGE: 0.15W; NV_NAME: 3904; NV_PN: 300-1128-000; PACK_TYPE: SOT323_1B1C1E; PATH: I91; PHYS_PAGE: 17; ROT: 2; SEC: 1; VER: 1; V_BE_GS: 6V; V_CE_SAT: 0.3V; XY: (-6100,6200)
R384 = R: ASSEMBLY: EDP; CDS_LIB: discrete; CDS_PART_NAME: R_0402-10K,5 %,62.5MW,195-0486-000; CDS_PHYS_PART_NAME: R_0402-10K,5 %,62.5MW,195-0486-000-10K,195-0486-000; CDS_SEC: 1; DEVICE_TYPENAME: R_0402-10K5625MW195-0486-000-10K195-0486-000; DRAWING: @P3449_B01_LIB.P3449_B01(SCH_1):PAGE17; MAX_WATTAGE: 62.5mW; NV_PN: 195-0486-000; PATH: I50; PHYS_PAGE: 17; ROT: 2; SEC: 1; SIGNAL_MODEL: nv_res; TOL: 5%; VER: 2; XY: (-7200,6800)
R385 = R#1: ASSEMBLY: EDP; CDS_LIB: discrete; CDS_PART_NAME: R_0402-0OHM,0.05 OHM,62.5MW,195-2655-000; CDS_PHYS_PART_NAME: R_0402-0OHM,0.05 OHM,62.5MW,195-2655-000-0OHM,195-2655-000; CDS_SEC: 1; CHIPS_PART_NAME: R; DEVICE_TYPENAME: R_0402-0OHM005OHM625MW195-2655-000-0OHM195-2655-000; DRAWING: @P3449_B01_LIB.P3449_B01(SCH_1):PAGE17; MAX_WATTAGE: 62.5mW; NV_PN: 195-2655-000; PATH: I7; PHYS_PAGE: 17; PLACEMENT_NOTE: CoLayout with L501; ROT: 0; SEC: 1; SIGNAL_MODEL: nv_res; TOL: 0.05 ohm; VER: 1; XY: (-6850,4750)
R386 = R#1: ASSEMBLY: EDP; CDS_LIB: discrete; CDS_PART_NAME: R_0402-0OHM,0.05 OHM,62.5MW,195-2655-000; CDS_PHYS_PART_NAME: R_0402-0OHM,0.05 OHM,62.5MW,195-2655-000-0OHM,195-2655-000; CDS_SEC: 1; CHIPS_PART_NAME: R; DEVICE_TYPENAME: R_0402-0OHM005OHM625MW195-2655-000-0OHM195-2655-000; DRAWING: @P3449_B01_LIB.P3449_B01(SCH_1):PAGE17; MAX_WATTAGE: 62.5mW; NV_PN: 195-2655-000; PATH: I12; PHYS_PAGE: 17; PLACEMENT_NOTE: CoLayout with L501; ROT: 0; SEC: 1; SIGNAL_MODEL: nv_res; TOL: 0.05 ohm; VER: 1; XY: (-6850,4400)
R387 = R#1: ASSEMBLY: EDP; CDS_LIB: discrete; CDS_PART_NAME: R_0402-0OHM,0.05 OHM,62.5MW,195-2655-000; CDS_PHYS_PART_NAME: R_0402-0OHM,0.05 OHM,62.5MW,195-2655-000-0OHM,195-2655-000; CDS_SEC: 1; CHIPS_PART_NAME: R; DEVICE_TYPENAME: R_0402-0OHM005OHM625MW195-2655-000-0OHM195-2655-000; DRAWING: @P3449_B01_LIB.P3449_B01(SCH_1):PAGE17; MAX_WATTAGE: 62.5mW; NV_PN: 195-2655-000; PATH: I13; PHYS_PAGE: 17; PLACEMENT_NOTE: CoLayout with L503; ROT: 0; SEC: 1; SIGNAL_MODEL: nv_res; TOL: 0.05 ohm; VER: 1; XY: (-6850,4250)
R388 = R#1: ASSEMBLY: EDP; CDS_LIB: discrete; CDS_PART_NAME: R_0402-0OHM,0.05 OHM,62.5MW,195-2655-000; CDS_PHYS_PART_NAME: R_0402-0OHM,0.05 OHM,62.5MW,195-2655-000-0OHM,195-2655-000; CDS_SEC: 1; CHIPS_PART_NAME: R; DEVICE_TYPENAME: R_0402-0OHM005OHM625MW195-2655-000-0OHM195-2655-000; DRAWING: @P3449_B01_LIB.P3449_B01(SCH_1):PAGE17; MAX_WATTAGE: 62.5mW; NV_PN: 195-2655-000; PATH: I15; PHYS_PAGE: 17; PLACEMENT_NOTE: CoLayout with L503; ROT: 0; SEC: 1; SIGNAL_MODEL: nv_res; TOL: 0.05 ohm; VER: 1; XY: (-6850,3900)
R389 = R#1: ASSEMBLY: EDP; CDS_LIB: discrete; CDS_PART_NAME: R_0402-0OHM,0.05 OHM,62.5MW,195-2655-000; CDS_PHYS_PART_NAME: R_0402-0OHM,0.05 OHM,62.5MW,195-2655-000-0OHM,195-2655-000; CDS_SEC: 1; CHIPS_PART_NAME: R; DEVICE_TYPENAME: R_0402-0OHM005OHM625MW195-2655-000-0OHM195-2655-000; DRAWING: @P3449_B01_LIB.P3449_B01(SCH_1):PAGE17; MAX_WATTAGE: 62.5mW; NV_PN: 195-2655-000; PATH: I16; PHYS_PAGE: 17; PLACEMENT_NOTE: CoLayout with L504; ROT: 0; SEC: 1; SIGNAL_MODEL: nv_res; TOL: 0.05 ohm; VER: 1; XY: (-6850,3750)
R390 = R#1: ASSEMBLY: EDP; CDS_LIB: discrete; CDS_PART_NAME: R_0402-0OHM,0.05 OHM,62.5MW,195-2655-000; CDS_PHYS_PART_NAME: R_0402-0OHM,0.05 OHM,62.5MW,195-2655-000-0OHM,195-2655-000; CDS_SEC: 1; CHIPS_PART_NAME: R; DEVICE_TYPENAME: R_0402-0OHM005OHM625MW195-2655-000-0OHM195-2655-000; DRAWING: @P3449_B01_LIB.P3449_B01(SCH_1):PAGE17; MAX_WATTAGE: 62.5mW; NV_PN: 195-2655-000; PATH: I18; PHYS_PAGE: 17; PLACEMENT_NOTE: CoLayout with L504; ROT: 0; SEC: 1; SIGNAL_MODEL: nv_res; TOL: 0.05 ohm; VER: 1; XY: (-6850,3400)
R391 = R#1: ASSEMBLY: EDP; CDS_LIB: discrete; CDS_PART_NAME: R_0402-0OHM,0.05 OHM,62.5MW,195-2655-000; CDS_PHYS_PART_NAME: R_0402-0OHM,0.05 OHM,62.5MW,195-2655-000-0OHM,195-2655-000; CDS_SEC: 1; CHIPS_PART_NAME: R; DEVICE_TYPENAME: R_0402-0OHM005OHM625MW195-2655-000-0OHM195-2655-000; DRAWING: @P3449_B01_LIB.P3449_B01(SCH_1):PAGE17; MAX_WATTAGE: 62.5mW; NV_PN: 195-2655-000; PATH: I19; PHYS_PAGE: 17; PLACEMENT_NOTE: CoLayout with L506; ROT: 0; SEC: 1; SIGNAL_MODEL: nv_res; TOL: 0.05 ohm; VER: 1; XY: (-6850,3250)
R392 = R#1: ASSEMBLY: EDP; CDS_LIB: discrete; CDS_PART_NAME: R_0402-0OHM,0.05 OHM,62.5MW,195-2655-000; CDS_PHYS_PART_NAME: R_0402-0OHM,0.05 OHM,62.5MW,195-2655-000-0OHM,195-2655-000; CDS_SEC: 1; CHIPS_PART_NAME: R; DEVICE_TYPENAME: R_0402-0OHM005OHM625MW195-2655-000-0OHM195-2655-000; DRAWING: @P3449_B01_LIB.P3449_B01(SCH_1):PAGE17; MAX_WATTAGE: 62.5mW; NV_PN: 195-2655-000; PATH: I21; PHYS_PAGE: 17; PLACEMENT_NOTE: CoLayout with L506; ROT: 0; SEC: 1; SIGNAL_MODEL: nv_res; TOL: 0.05 ohm; VER: 1; XY: (-6850,2900)
R396 = R: ASSEMBLY: EDP; CDS_LIB: discrete; CDS_PART_NAME: R_0402-100K,1 %,62.5MW,195-0005-000; CDS_PHYS_PART_NAME: R_0402-100K,1 %,62.5MW,195-0005-000-100K,195-0005-000; CDS_SEC: 1; DEVICE_TYPENAME: R_0402-100K1625MW195-0005-000-100K195-0005-000; DRAWING: @P3449_B01_LIB.P3449_B01(SCH_1):PAGE17; MAX_WATTAGE: 62.5mW; NV_PN: 195-0005-000; PATH: I57; PHYS_PAGE: 17; ROT: 2; SEC: 1; SIGNAL_MODEL: nv_res; TOL: 1%; VER: 2; XY: (-4750,5200)
R397 = R: ASSEMBLY: EDP; CDS_LIB: discrete; CDS_PART_NAME: R_0402-100K,1 %,62.5MW,195-0005-000; CDS_PHYS_PART_NAME: R_0402-100K,1 %,62.5MW,195-0005-000-100K,195-0005-000; CDS_SEC: 1; DEVICE_TYPENAME: R_0402-100K1625MW195-0005-000-100K195-0005-000; DRAWING: @P3449_B01_LIB.P3449_B01(SCH_1):PAGE17; MAX_WATTAGE: 62.5mW; NV_PN: 195-0005-000; PATH: I58; PHYS_PAGE: 17; ROT: 2; SEC: 1; SIGNAL_MODEL: nv_res; TOL: 1%; VER: 2; XY: (-4450,5700)
R463 = R#1: ASSEMBLY: EDP; CDS_LIB: discrete; CDS_PART_NAME: R_0402-0OHM,0.05 OHM,62.5MW,195-2655-000; CDS_PHYS_PART_NAME: R_0402-0OHM,0.05 OHM,62.5MW,195-2655-000-0OHM,195-2655-000; CDS_SEC: 1; CHIPS_PART_NAME: R; DEVICE_TYPENAME: R_0402-0OHM005OHM625MW195-2655-000-0OHM195-2655-000; DRAWING: @P3449_B01_LIB.P3449_B01(SCH_1):PAGE17; MAX_WATTAGE: 62.5mW; NV_PN: 195-2655-000; PATH: I83; PHYS_PAGE: 17; ROT: 2; SEC: 1; SIGNAL_MODEL: nv_res; TOL: 0.05 ohm; VER: 1; XY: (-2750,5900)
R464 = R: ASSEMBLY: EDP; CDS_LIB: discrete; CDS_PART_NAME: R_0402-24.9K,1 %,62.5MW,195-0195-000; CDS_PHYS_PART_NAME: R_0402-24.9K,1 %,62.5MW,195-0195-000-195-0195-000,24.9K; CDS_SEC: 1; DEVICE_TYPENAME: R_0402-249K1625MW195-0195-000-195-0195-000249K; DRAWING: @P3449_B01_LIB.P3449_B01(SCH_1):PAGE17; MAX_WATTAGE: 62.5mW; NV_PN: 195-0195-000; PATH: I84; PHYS_PAGE: 17; ROT: 0; SEC: 1; SIGNAL_MODEL: nv_res; TOL: 1%; VER: 2; XY: (-1150,5600)
R498 = R: ASSEMBLY: EDP; CDS_LIB: discrete; CDS_PART_NAME: R_0402-5.1K,5 %,62.5MW,195-0605-000; CDS_PHYS_PART_NAME: R_0402-5.1K,5 %,62.5MW,195-0605-000-195-0605-000,5.1K; CDS_SEC: 1; DEVICE_TYPENAME: R_0402-51K5625MW195-0605-000-195-0605-00051K; DRAWING: @P3449_B01_LIB.P3449_B01(SCH_1):PAGE17; MAX_WATTAGE: 62.5mW; NV_PN: 195-0605-000; PATH: I93; PHYS_PAGE: 17; ROT: 2; SEC: 1; SIGNAL_MODEL: nv_res; TOL: 5%; VER: 2; XY: (-6250,6800)
R499 = R: ASSEMBLY: EDP; CDS_LIB: discrete; CDS_PART_NAME: R_0402-10K,5 %,62.5MW,195-0486-000; CDS_PHYS_PART_NAME: R_0402-10K,5 %,62.5MW,195-0486-000-10K,195-0486-000; CDS_SEC: 1; DEVICE_TYPENAME: R_0402-10K5625MW195-0486-000-10K195-0486-000; DRAWING: @P3449_B01_LIB.P3449_B01(SCH_1):PAGE17; MAX_WATTAGE: 62.5mW; NV_PN: 195-0486-000; PATH: I95; PHYS_PAGE: 17; ROT: 2; SEC: 1; SIGNAL_MODEL: nv_res; TOL: 5%; VER: 2; XY: (-5700,6000)
R500 = R: ASSEMBLY: EDP; CDS_LIB: discrete; CDS_PART_NAME: R_0402-10K,5 %,62.5MW,195-0486-000; CDS_PHYS_PART_NAME: R_0402-10K,5 %,62.5MW,195-0486-000-10K,195-0486-000; CDS_SEC: 1; DEVICE_TYPENAME: R_0402-10K5625MW195-0486-000-10K195-0486-000; DRAWING: @P3449_B01_LIB.P3449_B01(SCH_1):PAGE17; MAX_WATTAGE: 62.5mW; NV_PN: 195-0486-000; PATH: I94; PHYS_PAGE: 17; ROT: 3; SEC: 1; SIGNAL_MODEL: nv_res; TOL: 5%; VER: 2; XY: (-5550,6200)
R509 = R#1: CDS_LIB: discrete; CDS_PART_NAME: R_0402-5.1K,5 %,62.5MW,195-0605-000; CDS_PHYS_PART_NAME: R_0402-5.1K,5 %,62.5MW,195-0605-000-195-0605-000,5.1K; CDS_SEC: 1; CHIPS_PART_NAME: R; DEVICE_TYPENAME: R_0402-51K5625MW195-0605-000-195-0605-00051K; DRAWING: @P3449_B01_LIB.P3449_B01(SCH_1):PAGE17; MAX_WATTAGE: 62.5mW; NV_PN: 195-0605-000; PATH: I96; PHYS_PAGE: 17; ROT: 0; SEC: 1; SIGNAL_MODEL: nv_res; TOL: 5%; VER: 1; XY: (-6600,6400)
U61 = U_PWR_SW_UL: ASSEMBLY: EDP; CDS_LIB: power_supply; CDS_PART_NAME: U_PWR_SW_UL_SOT23_5_EFU-APL3552ABI-TRG,2.7V..5.5V,2.7V..5.5V,2A,SWITCH,315-1062-000; CDS_PHYS_PART_NAME: U_PWR_SW_UL_SOT23_5_EFU-APL3552ABI-TRG,2.7V..5.5V,2.7V..5.5V,2A,SWITCH,315-1062-000-315-1062-000; CDS_SEC: 1; DEVICE_TYPENAME: U_PWR_SW_UL_SOT23_5_EFU-APL3552ABI-TRG27V55V27V55V2ASWITCH315-1062-000-315-1062-000; DRAWING: @P3449_B01_LIB.P3449_B01(SCH_1):PAGE17; FUNCTION: Power Switch; MAX_CURRENT: 2A; MAX_VOLTAGE: 2.7V..5.5V; NV_NAME: APL3552ABI-TRG; NV_PN: 315-1062-000; OUTPUT_VOLTAGE: 2.7V..5.5V; PACK_TYPE: SOT23_5_EFU; PATH: I80; PHYS_PAGE: 17; ROT: 0; SEC: 1; TYPE: Switch; VER: 1; XY: (-1850,5900)
C292 = C#1: ASSEMBLY: CAM; CDS_LIB: discrete; CDS_PART_NAME: C_0402-0.1UF,X5R,10%,6.3V,039-0007-000; CDS_PHYS_PART_NAME: C_0402-0.1UF,X5R,10%,6.3V,039-0007-000-0.1UF,039-0007-000; CDS_SEC: 1; CHIPS_PART_NAME: C; DEVICE_TYPENAME: C_0402-01UFX5R1063V039-0007-000-01UF039-0007-000; DRAWING: @P3449_B01_LIB.P3449_B01(SCH_1):PAGE18; ESL: N/A; ESR: N/A; MAT: X5R; MAX_VOLTAGE: 6.3V; NV_PN: 039-0007-000; PATH: I15; PHYS_PAGE: 18; ROT: 2; SEC: 1; SIGNAL_MODEL: nv_cap; TOL: 10%; VER: 1; XY: (-2800,5100)
D49 = D_ESD: ASSEMBLY: CAM; BREAKDOWN_VOLTAGE_MIN_TYP: 5.5V; CAPACITANCE_MAX_TYP: 1.2pF; CDS_LIB: discrete; CDS_PART_NAME: D_ESD_NORM-LESD5VD8LCG-R,1 LINE,BI-DIRECTIONAL,5V,0.05UA,5.5V,10V@2A,1.2PF,090-0172-000; CDS_PHYS_PART_NAME: D_ESD_NORM-LESD5VD8LCG-R,1 LINE,BI-DIRECTIONAL,5V,0.05UA,5.5V,10V@2A,1.2PF,090-0172-000-090-0172-000; CDS_SEC: 1; CLAMPING_VOLTAGE: 10V@2A; CONFIGURATION: 1 Line; DEVICE_TYPENAME: D_ESD_NORM-LESD5VD8LCG-R1LINEBI-DIRECTIONAL5V005UA55V10V2A12PF090-0172-000-090-0172-000; DRAWING: @P3449_B01_LIB.P3449_B01(SCH_1):PAGE18; MAX_REVERSE_LEAKAGE_CURRENT: 0.05uA; MAX_REVERSE_VOLTAGE: 5V; NV_NAME: LESD5VD8LCG-R; NV_PN: 090-0172-000; PACK_TYPE: NORM; PATH: I32; PHYS_PAGE: 18; POLARITY: Bi-Directional; ROT: 0; SEC: 1; VER: 2; XY: (-7000,5300)
D51 = D_ESD: ASSEMBLY: CAM; BREAKDOWN_VOLTAGE_MIN_TYP: 5.5V; CAPACITANCE_MAX_TYP: 1.2pF; CDS_LIB: discrete; CDS_PART_NAME: D_ESD_NORM-LESD5VD8LCG-R,1 LINE,BI-DIRECTIONAL,5V,0.05UA,5.5V,10V@2A,1.2PF,090-0172-000; CDS_PHYS_PART_NAME: D_ESD_NORM-LESD5VD8LCG-R,1 LINE,BI-DIRECTIONAL,5V,0.05UA,5.5V,10V@2A,1.2PF,090-0172-000-090-0172-000; CDS_SEC: 1; CLAMPING_VOLTAGE: 10V@2A; CONFIGURATION: 1 Line; DEVICE_TYPENAME: D_ESD_NORM-LESD5VD8LCG-R1LINEBI-DIRECTIONAL5V005UA55V10V2A12PF090-0172-000-090-0172-000; DRAWING: @P3449_B01_LIB.P3449_B01(SCH_1):PAGE18; MAX_REVERSE_LEAKAGE_CURRENT: 0.05uA; MAX_REVERSE_VOLTAGE: 5V; NV_NAME: LESD5VD8LCG-R; NV_PN: 090-0172-000; PACK_TYPE: NORM; PATH: I33; PHYS_PAGE: 18; POLARITY: Bi-Directional; ROT: 0; SEC: 1; VER: 2; XY: (-6500,5300)
D53 = D_ESD: ASSEMBLY: CAM; BREAKDOWN_VOLTAGE_MIN_TYP: 5.5V; CAPACITANCE_MAX_TYP: 1.2pF; CDS_LIB: discrete; CDS_PART_NAME: D_ESD_NORM-LESD5VD8LCG-R,1 LINE,BI-DIRECTIONAL,5V,0.05UA,5.5V,10V@2A,1.2PF,090-0172-000; CDS_PHYS_PART_NAME: D_ESD_NORM-LESD5VD8LCG-R,1 LINE,BI-DIRECTIONAL,5V,0.05UA,5.5V,10V@2A,1.2PF,090-0172-000-090-0172-000; CDS_SEC: 1; CLAMPING_VOLTAGE: 10V@2A; CONFIGURATION: 1 Line; DEVICE_TYPENAME: D_ESD_NORM-LESD5VD8LCG-R1LINEBI-DIRECTIONAL5V005UA55V10V2A12PF090-0172-000-090-0172-000; DRAWING: @P3449_B01_LIB.P3449_B01(SCH_1):PAGE18; MAX_REVERSE_LEAKAGE_CURRENT: 0.05uA; MAX_REVERSE_VOLTAGE: 5V; NV_NAME: LESD5VD8LCG-R; NV_PN: 090-0172-000; PACK_TYPE: NORM; PATH: I35; PHYS_PAGE: 18; POLARITY: Bi-Directional; ROT: 0; SEC: 1; VER: 2; XY: (-5950,5300)
D55 = D_ESD: ASSEMBLY: CAM; BREAKDOWN_VOLTAGE_MIN_TYP: 5.5V; CAPACITANCE_MAX_TYP: 1.2pF; CDS_LIB: discrete; CDS_PART_NAME: D_ESD_NORM-LESD5VD8LCG-R,1 LINE,BI-DIRECTIONAL,5V,0.05UA,5.5V,10V@2A,1.2PF,090-0172-000; CDS_PHYS_PART_NAME: D_ESD_NORM-LESD5VD8LCG-R,1 LINE,BI-DIRECTIONAL,5V,0.05UA,5.5V,10V@2A,1.2PF,090-0172-000-090-0172-000; CDS_SEC: 1; CLAMPING_VOLTAGE: 10V@2A; CONFIGURATION: 1 Line; DEVICE_TYPENAME: D_ESD_NORM-LESD5VD8LCG-R1LINEBI-DIRECTIONAL5V005UA55V10V2A12PF090-0172-000-090-0172-000; DRAWING: @P3449_B01_LIB.P3449_B01(SCH_1):PAGE18; MAX_REVERSE_LEAKAGE_CURRENT: 0.05uA; MAX_REVERSE_VOLTAGE: 5V; NV_NAME: LESD5VD8LCG-R; NV_PN: 090-0172-000; PACK_TYPE: NORM; PATH: I34; PHYS_PAGE: 18; POLARITY: Bi-Directional; ROT: 0; SEC: 1; VER: 2; XY: (-5450,5300)
D57 = D_ESD: ASSEMBLY: CAM; BREAKDOWN_VOLTAGE_MIN_TYP: 5.5V; CAPACITANCE_MAX_TYP: 1.2pF; CDS_LIB: discrete; CDS_PART_NAME: D_ESD_NORM-LESD5VD8LCG-R,1 LINE,BI-DIRECTIONAL,5V,0.05UA,5.5V,10V@2A,1.2PF,090-0172-000; CDS_PHYS_PART_NAME: D_ESD_NORM-LESD5VD8LCG-R,1 LINE,BI-DIRECTIONAL,5V,0.05UA,5.5V,10V@2A,1.2PF,090-0172-000-090-0172-000; CDS_SEC: 1; CLAMPING_VOLTAGE: 10V@2A; CONFIGURATION: 1 Line; DEVICE_TYPENAME: D_ESD_NORM-LESD5VD8LCG-R1LINEBI-DIRECTIONAL5V005UA55V10V2A12PF090-0172-000-090-0172-000; DRAWING: @P3449_B01_LIB.P3449_B01(SCH_1):PAGE18; MAX_REVERSE_LEAKAGE_CURRENT: 0.05uA; MAX_REVERSE_VOLTAGE: 5V; NV_NAME: LESD5VD8LCG-R; NV_PN: 090-0172-000; PACK_TYPE: NORM; PATH: I37; PHYS_PAGE: 18; POLARITY: Bi-Directional; ROT: 0; SEC: 1; VER: 2; XY: (-4900,5300)
D59 = D_ESD: ASSEMBLY: CAM; BREAKDOWN_VOLTAGE_MIN_TYP: 5.5V; CAPACITANCE_MAX_TYP: 1.2pF; CDS_LIB: discrete; CDS_PART_NAME: D_ESD_NORM-LESD5VD8LCG-R,1 LINE,BI-DIRECTIONAL,5V,0.05UA,5.5V,10V@2A,1.2PF,090-0172-000; CDS_PHYS_PART_NAME: D_ESD_NORM-LESD5VD8LCG-R,1 LINE,BI-DIRECTIONAL,5V,0.05UA,5.5V,10V@2A,1.2PF,090-0172-000-090-0172-000; CDS_SEC: 1; CLAMPING_VOLTAGE: 10V@2A; CONFIGURATION: 1 Line; DEVICE_TYPENAME: D_ESD_NORM-LESD5VD8LCG-R1LINEBI-DIRECTIONAL5V005UA55V10V2A12PF090-0172-000-090-0172-000; DRAWING: @P3449_B01_LIB.P3449_B01(SCH_1):PAGE18; MAX_REVERSE_LEAKAGE_CURRENT: 0.05uA; MAX_REVERSE_VOLTAGE: 5V; NV_NAME: LESD5VD8LCG-R; NV_PN: 090-0172-000; PACK_TYPE: NORM; PATH: I36; PHYS_PAGE: 18; POLARITY: Bi-Directional; ROT: 0; SEC: 1; VER: 2; XY: (-4400,5300)
D67 = D_ESD: ASSEMBLY: CAM; BREAKDOWN_VOLTAGE_MIN_TYP: 5.5V; CAPACITANCE_MAX_TYP: 1.2pF; CDS_LIB: discrete; CDS_PART_NAME: D_ESD_NORM-LESD5VD8LCG-R,1 LINE,BI-DIRECTIONAL,5V,0.05UA,5.5V,10V@2A,1.2PF,090-0172-000; CDS_PHYS_PART_NAME: D_ESD_NORM-LESD5VD8LCG-R,1 LINE,BI-DIRECTIONAL,5V,0.05UA,5.5V,10V@2A,1.2PF,090-0172-000-090-0172-000; CDS_SEC: 1; CLAMPING_VOLTAGE: 10V@2A; CONFIGURATION: 1 Line; DEVICE_TYPENAME: D_ESD_NORM-LESD5VD8LCG-R1LINEBI-DIRECTIONAL5V005UA55V10V2A12PF090-0172-000-090-0172-000; DRAWING: @P3449_B01_LIB.P3449_B01(SCH_1):PAGE18; MAX_REVERSE_LEAKAGE_CURRENT: 0.05uA; MAX_REVERSE_VOLTAGE: 5V; NV_NAME: LESD5VD8LCG-R; NV_PN: 090-0172-000; PACK_TYPE: NORM; PATH: I73; PHYS_PAGE: 18; POLARITY: Bi-Directional; ROT: 0; SEC: 1; VER: 2; XY: (-4900,1650)
D68 = D_ESD: ASSEMBLY: CAM; BREAKDOWN_VOLTAGE_MIN_TYP: 5.5V; CAPACITANCE_MAX_TYP: 1.2pF; CDS_LIB: discrete; CDS_PART_NAME: D_ESD_NORM-LESD5VD8LCG-R,1 LINE,BI-DIRECTIONAL,5V,0.05UA,5.5V,10V@2A,1.2PF,090-0172-000; CDS_PHYS_PART_NAME: D_ESD_NORM-LESD5VD8LCG-R,1 LINE,BI-DIRECTIONAL,5V,0.05UA,5.5V,10V@2A,1.2PF,090-0172-000-090-0172-000; CDS_SEC: 1; CLAMPING_VOLTAGE: 10V@2A; CONFIGURATION: 1 Line; DEVICE_TYPENAME: D_ESD_NORM-LESD5VD8LCG-R1LINEBI-DIRECTIONAL5V005UA55V10V2A12PF090-0172-000-090-0172-000; DRAWING: @P3449_B01_LIB.P3449_B01(SCH_1):PAGE18; MAX_REVERSE_LEAKAGE_CURRENT: 0.05uA; MAX_REVERSE_VOLTAGE: 5V; NV_NAME: LESD5VD8LCG-R; NV_PN: 090-0172-000; PACK_TYPE: NORM; PATH: I74; PHYS_PAGE: 18; POLARITY: Bi-Directional; ROT: 0; SEC: 1; VER: 2; XY: (-4350,1650)
J13 = CON_FPC_15: ANGLE: 0; ASSEMBLY: CAM; CDS_LIB: electro_mechanic; CDS_PART_NAME: CON_FPC_15_SMD15_TE-1-1734248-5,FEMALE,1MM,0,YES,YES,[ ],NO,NO,N/A,N/A,080-1669-000; CDS_PHYS_PART_NAME: CON_FPC_15_SMD15_TE-1-1734248-5,FEMALE,1MM,0,YES,YES,[ ],NO,NO,N/A,N/A,080-1669-000-080-1669-000; CDS_SEC: 1; DEVICE_TYPENAME: CON_FPC_15_SMD15_TE-1-1734248-5FEMALE1MM0YESYESNONONANA080-1669-000-080-1669-000; DRAWING: @P3449_B01_LIB.P3449_B01(SCH_1):PAGE18; EMI_GROUND_TAB: No; GENDER: Female; LATCHING: [ ]; MAX_CURRENT: N/A; MAX_VOLTAGE: N/A; NV_NAME: 1-1734248-5; NV_PN: 080-1669-000; PACK_TYPE: SMD15_TE; PATH: I14; PHYS_PAGE: 18; PITCH: 1mm; REFLOW: Yes; ROT: 0; SEC: 1; SEC_TYPE: SMD15_TE; SHIELDED: No; SHROUDED: YES; VER: 3; XY: (-1950,5800)
R484 = R: ASSEMBLY: CAM; CDS_LIB: discrete; CDS_PART_NAME: R_0402-10K,5 %,62.5MW,195-0486-000; CDS_PHYS_PART_NAME: R_0402-10K,5 %,62.5MW,195-0486-000-10K,195-0486-000; CDS_SEC: 1; DEVICE_TYPENAME: R_0402-10K5625MW195-0486-000-10K195-0486-000; DRAWING: @P3449_B01_LIB.P3449_B01(SCH_1):PAGE18; MAX_WATTAGE: 62.5mW; NV_PN: 195-0486-000; PATH: I92; PHYS_PAGE: 18; ROT: 0; SEC: 1; SIGNAL_MODEL: nv_res; TOL: 5%; VER: 2; XY: (-10850,1350)
R485 = R: ASSEMBLY: CAM; CDS_LIB: discrete; CDS_PART_NAME: R_0402-47K,5 %,62.5MW,195-0599-000; CDS_PHYS_PART_NAME: R_0402-47K,5 %,62.5MW,195-0599-000-195-0599-000,47K; CDS_SEC: 1; DEVICE_TYPENAME: R_0402-47K5625MW195-0599-000-195-0599-00047K; DRAWING: @P3449_B01_LIB.P3449_B01(SCH_1):PAGE18; MAX_WATTAGE: 62.5mW; NV_PN: 195-0599-000; PATH: I86; PHYS_PAGE: 18; ROT: 0; SEC: 1; SIGNAL_MODEL: nv_res; TOL: 5%; VER: 2; XY: (-9200,2300)
R486 = R#1: ASSEMBLY: CAM; CDS_LIB: discrete; CDS_PART_NAME: R_0402-0OHM,0.05 OHM,62.5MW,195-2655-000; CDS_PHYS_PART_NAME: R_0402-0OHM,0.05 OHM,62.5MW,195-2655-000-0OHM,195-2655-000; CDS_SEC: 1; CHIPS_PART_NAME: R; DEVICE_TYPENAME: R_0402-0OHM005OHM625MW195-2655-000-0OHM195-2655-000; DRAWING: @P3449_B01_LIB.P3449_B01(SCH_1):PAGE18; MAX_WATTAGE: 62.5mW; NV_PN: 195-2655-000; PATH: I94; PHYS_PAGE: 18; ROT: 0; SEC: 1; SIGNAL_MODEL: nv_res; TOL: 0.05 ohm; VER: 1; XY: (-9050,1450)
R488 = R: ASSEMBLY: CAM; CDS_LIB: discrete; CDS_PART_NAME: R_0402-47K,5 %,62.5MW,195-0599-000; CDS_PHYS_PART_NAME: R_0402-47K,5 %,62.5MW,195-0599-000-195-0599-000,47K; CDS_SEC: 1; DEVICE_TYPENAME: R_0402-47K5625MW195-0599-000-195-0599-00047K; DRAWING: @P3449_B01_LIB.P3449_B01(SCH_1):PAGE18; MAX_WATTAGE: 62.5mW; NV_PN: 195-0599-000; PATH: I88; PHYS_PAGE: 18; ROT: 0; SEC: 1; SIGNAL_MODEL: nv_res; TOL: 5%; VER: 2; XY: (-8700,2300)
TP97 = LABTESTPOINT: CDS_LIB: electro_mechanic; CDS_PART_NAME: LABTESTPOINT_PIN-LTPB071C125; CDS_PHYS_PART_NAME: LABTESTPOINT_PIN-LTPB071C125; CDS_SEC: 1; DEVICE_TYPENAME: LABTESTPOINT_PIN-LTPB071C125; DRAWING: @P3449_B01_LIB.P3449_B01(SCH_1):PAGE18; NV_NAME: LTPB071C125; PACK_TYPE: PIN; PATH: I71; PHYS_PAGE: 18; ROT: 0; SEC: 1; VER: 1; XY: (-4350,6550)
TP98 = LABTESTPOINT: CDS_LIB: electro_mechanic; CDS_PART_NAME: LABTESTPOINT_PIN-LTPB071C125; CDS_PHYS_PART_NAME: LABTESTPOINT_PIN-LTPB071C125; CDS_SEC: 1; DEVICE_TYPENAME: LABTESTPOINT_PIN-LTPB071C125; DRAWING: @P3449_B01_LIB.P3449_B01(SCH_1):PAGE18; NV_NAME: LTPB071C125; PACK_TYPE: PIN; PATH: I66; PHYS_PAGE: 18; ROT: 0; SEC: 1; VER: 1; XY: (-4350,6500)
TP99 = LABTESTPOINT: CDS_LIB: electro_mechanic; CDS_PART_NAME: LABTESTPOINT_PIN-LTPB071C125; CDS_PHYS_PART_NAME: LABTESTPOINT_PIN-LTPB071C125; CDS_SEC: 1; DEVICE_TYPENAME: LABTESTPOINT_PIN-LTPB071C125; DRAWING: @P3449_B01_LIB.P3449_B01(SCH_1):PAGE18; NV_NAME: LTPB071C125; PACK_TYPE: PIN; PATH: I67; PHYS_PAGE: 18; ROT: 0; SEC: 1; VER: 1; XY: (-4350,6400)
TP100 = LABTESTPOINT: CDS_LIB: electro_mechanic; CDS_PART_NAME: LABTESTPOINT_PIN-LTPB071C125; CDS_PHYS_PART_NAME: LABTESTPOINT_PIN-LTPB071C125; CDS_SEC: 1; DEVICE_TYPENAME: LABTESTPOINT_PIN-LTPB071C125; DRAWING: @P3449_B01_LIB.P3449_B01(SCH_1):PAGE18; NV_NAME: LTPB071C125; PACK_TYPE: PIN; PATH: I68; PHYS_PAGE: 18; ROT: 0; SEC: 1; VER: 1; XY: (-4350,6350)
TP101 = LABTESTPOINT: CDS_LIB: electro_mechanic; CDS_PART_NAME: LABTESTPOINT_PIN-LTPB071C125; CDS_PHYS_PART_NAME: LABTESTPOINT_PIN-LTPB071C125; CDS_SEC: 1; DEVICE_TYPENAME: LABTESTPOINT_PIN-LTPB071C125; DRAWING: @P3449_B01_LIB.P3449_B01(SCH_1):PAGE18; NV_NAME: LTPB071C125; PACK_TYPE: PIN; PATH: I69; PHYS_PAGE: 18; ROT: 0; SEC: 1; VER: 1; XY: (-4350,6250)
TP102 = LABTESTPOINT: CDS_LIB: electro_mechanic; CDS_PART_NAME: LABTESTPOINT_PIN-LTPB071C125; CDS_PHYS_PART_NAME: LABTESTPOINT_PIN-LTPB071C125; CDS_SEC: 1; DEVICE_TYPENAME: LABTESTPOINT_PIN-LTPB071C125; DRAWING: @P3449_B01_LIB.P3449_B01(SCH_1):PAGE18; NV_NAME: LTPB071C125; PACK_TYPE: PIN; PATH: I70; PHYS_PAGE: 18; ROT: 0; SEC: 1; VER: 1; XY: (-4350,6200)
TP128 TP129 = LABTESTPOINT#1: CDS_LIB: electro_mechanic; CDS_LOCATION: TP51; CDS_PART_NAME: LABTESTPOINT_PIN-LTPB071C125; CDS_PHYS_PART_NAME: LABTESTPOINT_PIN-LTPB071C125; CDS_SEC: 1; DEVICE_TYPENAME: LABTESTPOINT_PIN-LTPB071C125; DRAWING: @P3449_B01_LIB.P3449_B01(SCH_1):PAGE5; LOCATION: TP51; NV_NAME: LTPB071C125; PACK_TYPE: PIN; PATH: I198; PHYS_PAGE: 5; ROT: 0; SEC: 1; VER: 3; XY: (-2450,5400)
U65 = U_SW_ANA_USB: ASSEMBLY: CAM; CDS_LIB: analog; CDS_PART_NAME: U_SW_ANA_USB_UQFN10-TS3USB30E,SWITCH - ANALOG,115-0655-000; CDS_PHYS_PART_NAME: U_SW_ANA_USB_UQFN10-TS3USB30E,SWITCH - ANALOG,115-0655-000-115-0655-000; CDS_SEC: 1; DEVICE_TYPENAME: U_SW_ANA_USB_UQFN10-TS3USB30ESWITCH-ANALOG115-0655-000-115-0655-000; DRAWING: @P3449_B01_LIB.P3449_B01(SCH_1):PAGE18; FUNCTION: Switch - Analog; NV_NAME: TS3USB30E; NV_PN: 115-0655-000; PACK_TYPE: UQFN10; PATH: I80; PHYS_PAGE: 18; ROT: 2; SEC: 1; VER: 3; XY: (-10050,1750)

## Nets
3V3_IO_PG: R463.2 ; also on sheet 10 14
GND: C291.2 C292.2 C322.2 D27.3(GND1) D28.3(GND1) D29.3(GND1) D49.2 D51.2 D53.2 D55.2 D57.2 D59.2 D67.2 D68.2 J6.21(GND_1) J6.24(GND_2) J6.27(GND_3) J6.30(GND_4) J6.35(GND_7) J6.38(PWR_RET) J13.1(PIN1) J13.7(PIN7) J13.13(PIN13) J13.19(PIN19) Q52.2(E) Q53.2(E) R396.2 R464.2 R484.2 R486.2 R499.2 U61.2(GND) U65.4(GND) ; also on sheet 2 3 6 7 8 9 10 11 12 13 14 15 18 22
VDD_1V8: R384.1 R498.1 ; also on sheet 2 3 6 8 10 18
VDD_3V3_EDP: C322.1 J6.39(PWR) U61.1(OUT)
VDD_3V3_SYS: C292.1 J13.29(PIN29) R397.1 R485.1 R488.1 U61.5(IN) U65.9(VCC) ; also on sheet 2 3 6 7 8 10 17 18
CAM0_I2C_SCL: J13.25(PIN25) R485.2 U65.1(HSD1P)
CAM0_I2C_SDA: J13.27(PIN27) R488.2 U65.7(HSD1N)
CAM0_MCLK: D67.1 J13.23(PIN23) ; also on sheet 17
CAM0_PWDN: D68.1 J13.21(PIN21) ; also on sheet 17
CAM1_I2C_SCL: TP128.1 U65.2(HSD2P)
CAM1_I2C_SDA: TP129.1 U65.6(HSD2N)
CAM_I2C_SCL: U65.3(DP) ; also on sheet 14 17
CAM_I2C_SDA: U65.5(DN) ; also on sheet 14 17
CAM_MUX_OE*: R486.1 U65.8(OE*)
CAM_MUX_SEL: R484.1 U65.10(S) ; also on sheet 17
CSI0_CLK_N: D57.1 J13.15(PIN15) TP98.1 ; also on sheet 17
CSI0_CLK_P: D59.1 J13.17(PIN17) TP97.1 ; also on sheet 17
CSI0_D0_N: D49.1 J13.3(PIN3) TP102.1 ; also on sheet 17
CSI0_D0_P: D51.1 J13.5(PIN5) TP101.1 ; also on sheet 17
CSI0_D1_N: D53.1 J13.9(PIN9) TP100.1 ; also on sheet 17
CSI0_D1_P: D55.1 J13.11(PIN11) TP99.1 ; also on sheet 17
DP0_AUX_CH0_N: C289.1 ; also on sheet 16
DP0_AUX_CH0_P: C290.1 ; also on sheet 16
DP0_HPD: Q52.3(C) R384.2 ; also on sheet 16
DP0_HPD_B: Q52.1(B) R509.1
DP0_HPD_B2: Q53.1(B) R499.1 R500.1
DP0_HPD_C: Q53.3(C) R498.2 R509.2
DP0_TXD0_N: C284.1 ; also on sheet 16
DP0_TXD0_P: C288.1 ; also on sheet 16
DP0_TXD1_N: C283.1 ; also on sheet 16
DP0_TXD1_P: C287.1 ; also on sheet 16
DP0_TXD2_N: C282.1 ; also on sheet 16
DP0_TXD2_P: C286.1 ; also on sheet 16
DP0_TXD3_N: C281.1 ; also on sheet 16
DP0_TXD3_P: C285.1 ; also on sheet 16
DP_AUX_CON_CH0_N: C289.2 D27.4(3A) D27.7(3B) J6.36(AUXN) R397.2
DP_AUX_CON_CH0_P: C290.2 D27.5(4A) D27.6(4B) J6.34(AUXP) R396.1
DP_CON_LANE0_N: D28.4(3A) D28.7(3B) J6.22(LANE_0N) L35.1 R391.2
DP_CON_LANE0_P: D28.5(4A) D28.6(4B) J6.20(LANE_0P) L35.2 R392.2
DP_CON_LANE1_N: D29.2(2A) D29.9(2B) J6.25(LANE_1N) L34.2 R389.2
DP_CON_LANE1_P: D29.1(1A) D29.10(1B) J6.23(LANE_1P) L34.1 R390.2
DP_CON_LANE2_N: D28.1(1A) D28.10(1B) J6.28(LANE_2N) L33.1 R387.2
DP_CON_LANE2_P: D28.2(2A) D28.9(2B) J6.26(LANE_2P) L33.2 R388.2
DP_CON_LANE3_N: D29.5(4A) D29.6(4B) J6.31(LANE_3N) L32.2 R385.2
DP_CON_LANE3_P: D29.4(3A) D29.7(3B) J6.29(LANE_3P) L32.1 R386.2
DP_HPD_CON: C291.1 D27.1(1A) D27.10(1B) J6.37(HPD) R500.2
DP_LANE0_N: C284.2 L35.4 R391.1
DP_LANE0_P: C288.2 L35.3 R392.1
DP_LANE1_N: C283.2 L34.3 R389.1
DP_LANE1_P: C287.2 L34.4 R390.1
DP_LANE2_N: C282.2 L33.4 R387.1
DP_LANE2_P: C286.2 L33.3 R388.1
DP_LANE3_N: C281.2 L32.3 R385.1
DP_LANE3_P: C285.2 L32.4 R386.1
EDP_ISET: R464.1 U61.3(OC*)
EDP_SW_EN: R463.1 U61.4(EN)
SNN_DP_CEC: J6.33(CEC_DP)
SNN_DP_MODE: J6.32(MODE)
SNN_ESD_D27: D27.2(2A) D27.9(2B)
SNN_J13_NC1: J13.2(PIN2)
SNN_J13_NC2: J13.4(PIN4)
SNN_J13_NC3: J13.6(PIN6)
SNN_J13_NC4: J13.8(PIN8)
SNN_J13_NC5: J13.10(PIN10)
SNN_J13_NC6: J13.12(PIN12)
SNN_J13_NC7: J13.14(PIN14)
SNN_J13_NC8: J13.16(PIN16)
SNN_J13_NC9: J13.18(PIN18)
SNN_J13_NC10: J13.20(PIN20)
SNN_J13_NC11: J13.22(PIN22)
SNN_J13_NC12: J13.24(PIN24)
SNN_J13_NC13: J13.26(PIN26)
SNN_J13_NC14: J13.28(PIN28)
SNN_J13_NC15: J13.30(PIN30)

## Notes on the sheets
sheet 4
- A
- B
- C
- D
- E
- F
- G
- H
- CSI CAM CONNECTOR
- 1
- 1
- 2
- 2
- 3
- 3
- 4
- 4
- 5
- 5
- NVIDIA CORPORATION
- 2701 SAN TOMAS
  EXPRESSWAY
- ASSEMBLY
- Jetson Nano Carrier Board
- SANTA CLARA, CA 95050, USA
- PAGE DETAIL
- CAM Connector
- NV_PN
- ALL NVIDIA DESIGN SPECIFICATIONS, REFERENCE SPECIFICATIONS, REFERENCE BOARDS, FILES, DRAWINGS, DIAGNOSTICS, LISTS AND OTHER DOCUMENTS OR INFORMATION (TOGETHER AND SEPARATELY, 'MATERIALS') ARE BEING PROVIDED 'AS IS'. THE MATERIALS
  MAY
- CONTAIN KNOWN AND UNKNOWN VIOLATIONS OR DEVIATIONS OF INDUSTRY STANDARDS AND SPECIFICATIONS. NVIDIA MAKES NO WARRANTIES, EXPRESSED, IMPLIED, STATUTORY OR OTHERWISE WITH RESPECT TO THE MATERIALS OR OTHERWISE, AND EXPRESSLY DISCLAIMS
  ALL
- PCB REV
- PAGE
- 18 OF 23
- IMPLIED WARRANTIES INCLUDING, WITHOUT LIMITATION, THE WARRANTIES OF DESIGN, OF NONINFRINGEMENT, MERCHANTABILITY OR FITNESS FOR A PARTICULAR PURPOSE, OR ARISING FROM A COURSE OF DEALING, TRADE USAGE, TRADE PRACTICE, OR INDUSTRY
  STANDARDS.
- BOM REV
- A
- DATE
- 08-MAY-2019
- A
- B
- C
- D
- E
- F
- G
- H
sheet 5
- A
- B
- C
- D
- E
- F
- G
- H
- DisplayPort Connector
- 1
- 1
- 2
- 2
- PCB CO-LAYOUT
- 3
- 3
- 4
- 4
- 5
- 5
- NVIDIA CORPORATION
- 2701 SAN TOMAS
  EXPRESSWAY
- ASSEMBLY
- Jetson Nano Carrier Board
- SANTA CLARA, CA 95050, USA
- PAGE DETAIL
- DisplayPort
- NV_PN
- ALL NVIDIA DESIGN SPECIFICATIONS, REFERENCE SPECIFICATIONS, REFERENCE BOARDS, FILES, DRAWINGS, DIAGNOSTICS, LISTS AND OTHER DOCUMENTS OR INFORMATION (TOGETHER AND SEPARATELY, 'MATERIALS') ARE BEING PROVIDED 'AS IS'. THE MATERIALS
  MAY
- CONTAIN KNOWN AND UNKNOWN VIOLATIONS OR DEVIATIONS OF INDUSTRY STANDARDS AND SPECIFICATIONS. NVIDIA MAKES NO WARRANTIES, EXPRESSED, IMPLIED, STATUTORY OR OTHERWISE WITH RESPECT TO THE MATERIALS OR OTHERWISE, AND EXPRESSLY DISCLAIMS
  ALL
- PCB REV
- PAGE
- 17 OF 23
- IMPLIED WARRANTIES INCLUDING, WITHOUT LIMITATION, THE WARRANTIES OF DESIGN, OF NONINFRINGEMENT, MERCHANTABILITY OR FITNESS FOR A PARTICULAR PURPOSE, OR ARISING FROM A COURSE OF DEALING, TRADE USAGE, TRADE PRACTICE, OR INDUSTRY
  STANDARDS.
- BOM REV
- A
- DATE
- 08-MAY-2019
- A
- B
- C
- D
- E
- F
- G
- H
